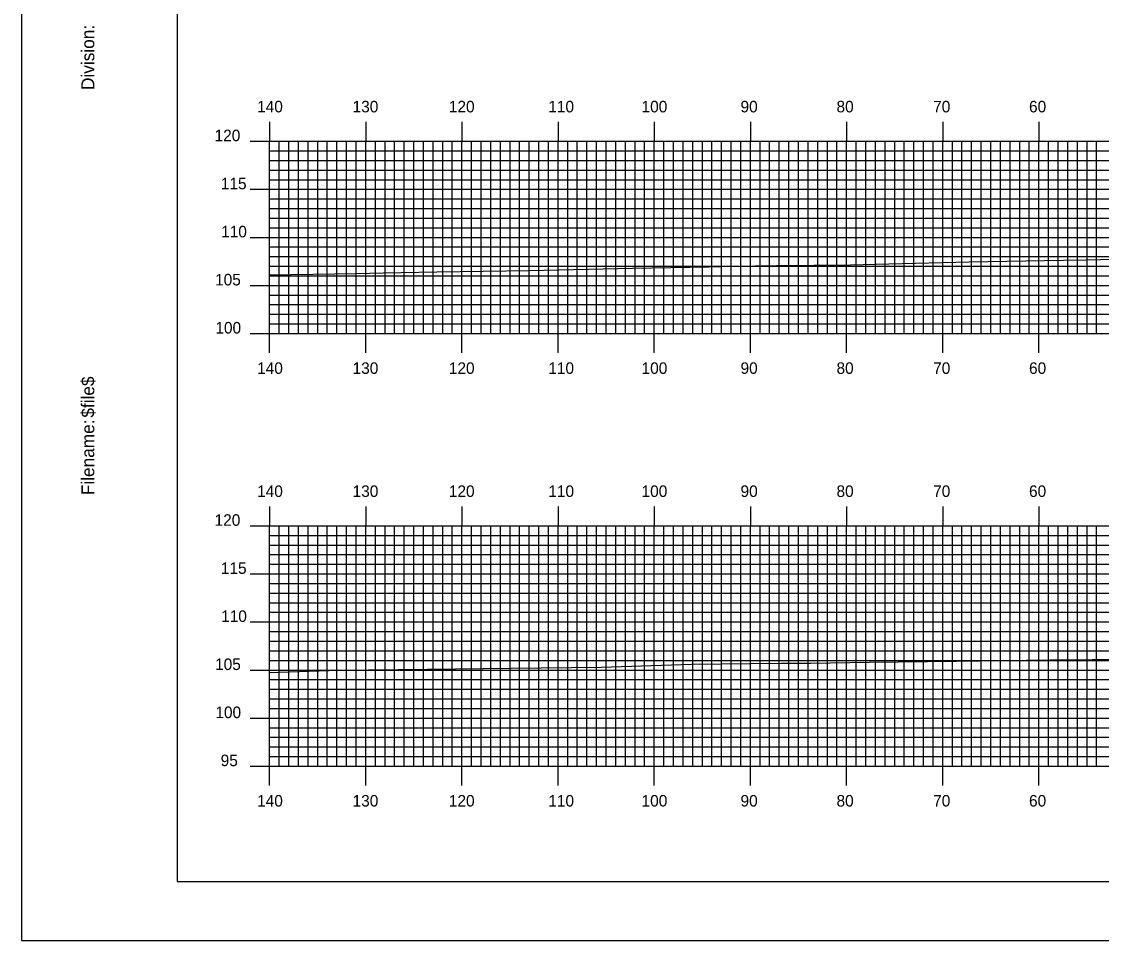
# Model space of a CAD drawing. Extents: x 1766120 to 1766463, y 442591 to 442811.
# Drawn here: x 1766119.6 to 1766231.9, y 442590.5 to 442686.1 of the extents above; entities that cross this region are included whole.
import ezdxf

# ---------------------------------------------------------------- set-up
doc = ezdxf.new("R2010")
doc.units = 0
for name, color, linetype in [('BORDER', 7, 'Continuous'), ('H_V ANNOTATION', 7, 'Continuous'), ('MAJOR', 7, 'Continuous'), ('MINOR', 7, 'Continuous'), ('PLOT BOUNDARY', 7, 'Continuous'), ('S_Roadway_Centerline', 7, 'Continuous')]:
    doc.layers.add(name, color=color, linetype=linetype)

msp = doc.modelspace()

# ---------------------------------------------------------------- linework, layer by layer
at = {"layer": 'BORDER'}
msp.add_lwpolyline([(1766135.8, 442596.67), (1766455.8, 442596.67), (1766455.8, 442806.67), (1766135.8, 442806.67)], close=True, dxfattribs=at)
at = {"layer": 'MAJOR'}
for p, q in [((1766145.4, 442675.67), (1766145.4, 442673.67)), ((1766155.4, 442675.67), (1766155.4, 442673.67)), ((1766165.4, 442675.67), (1766165.4, 442673.67)), ((1766175.4, 442675.67), (1766175.4, 442673.67)), ((1766185.4, 442675.67), (1766185.4, 442673.67)), ((1766195.4, 442675.67), (1766195.4, 442673.67)), ((1766205.4, 442675.67), (1766205.4, 442673.67)), ((1766215.4, 442675.67), (1766215.4, 442673.67)), ((1766225.4, 442675.67), (1766225.4, 442673.67)), ((1766143.39, 442673.67), (1766145.4, 442673.67)), ((1766145.4, 442673.67), (1766425.4, 442673.67)), ((1766145.4, 442653.67), (1766145.4, 442673.67)), ((1766145.4, 442653.67), (1766145.4, 442673.67)), ((1766145.4, 442673.67), (1766425.4, 442673.67)), ((1766155.4, 442653.67), (1766155.4, 442673.67)), ((1766165.4, 442653.67), (1766165.4, 442673.67)), ((1766175.4, 442653.67), (1766175.4, 442673.67)), ((1766185.4, 442653.67), (1766185.4, 442673.67)), ((1766195.4, 442653.67), (1766195.4, 442673.67)), ((1766205.4, 442653.67), (1766205.4, 442673.67)), ((1766215.4, 442653.67), (1766215.4, 442673.67)), ((1766225.4, 442653.67), (1766225.4, 442673.67)), ((1766143.39, 442668.67), (1766145.4, 442668.67)), ((1766145.4, 442668.67), (1766425.4, 442668.67)), ((1766143.39, 442663.67), (1766145.4, 442663.67)), ((1766145.4, 442663.67), (1766425.4, 442663.67)), ((1766143.39, 442658.67), (1766145.4, 442658.67)), ((1766145.4, 442658.67), (1766425.4, 442658.67)), ((1766143.39, 442653.67), (1766145.4, 442653.67)), ((1766145.4, 442653.67), (1766425.4, 442653.67)), ((1766145.4, 442653.67), (1766425.4, 442653.67)), ((1766145.4, 442651.66), (1766145.4, 442653.67)), ((1766155.4, 442651.66), (1766155.4, 442653.67)), ((1766165.4, 442651.66), (1766165.4, 442653.67)), ((1766175.4, 442651.66), (1766175.4, 442653.67)), ((1766185.4, 442651.66), (1766185.4, 442653.67)), ((1766195.4, 442651.66), (1766195.4, 442653.67)), ((1766205.4, 442651.66), (1766205.4, 442653.67)), ((1766215.4, 442651.66), (1766215.4, 442653.67)), ((1766225.4, 442651.66), (1766225.4, 442653.67)), ((1766145.4, 442635.67), (1766145.4, 442633.67)), ((1766155.4, 442635.67), (1766155.4, 442633.67)), ((1766165.4, 442635.67), (1766165.4, 442633.67)), ((1766175.4, 442635.67), (1766175.4, 442633.67)), ((1766185.4, 442635.67), (1766185.4, 442633.67)), ((1766195.4, 442635.67), (1766195.4, 442633.67)), ((1766205.4, 442635.67), (1766205.4, 442633.67)), ((1766215.4, 442635.67), (1766215.4, 442633.67)), ((1766225.4, 442635.67), (1766225.4, 442633.67)), ((1766143.39, 442633.67), (1766145.4, 442633.67)), ((1766145.4, 442633.67), (1766425.4, 442633.67)), ((1766145.4, 442608.67), (1766145.4, 442633.67)), ((1766145.4, 442608.67), (1766145.4, 442633.67)), ((1766145.4, 442633.67), (1766425.4, 442633.67)), ((1766155.4, 442608.67), (1766155.4, 442633.67)), ((1766165.4, 442608.67), (1766165.4, 442633.67)), ((1766175.4, 442608.67), (1766175.4, 442633.67)), ((1766185.4, 442608.67), (1766185.4, 442633.67)), ((1766195.4, 442608.67), (1766195.4, 442633.67)), ((1766205.4, 442608.67), (1766205.4, 442633.67)), ((1766215.4, 442608.67), (1766215.4, 442633.67)), ((1766225.4, 442608.67), (1766225.4, 442633.67)), ((1766143.39, 442628.67), (1766145.4, 442628.67)), ((1766145.4, 442628.67), (1766425.4, 442628.67)), ((1766143.39, 442623.67), (1766145.4, 442623.67)), ((1766145.4, 442623.67), (1766425.4, 442623.67)), ((1766143.39, 442618.67), (1766145.4, 442618.67)), ((1766145.4, 442618.67), (1766425.4, 442618.67)), ((1766143.39, 442613.67), (1766145.4, 442613.67)), ((1766145.4, 442613.67), (1766425.4, 442613.67)), ((1766143.39, 442608.67), (1766145.4, 442608.67)), ((1766145.4, 442608.67), (1766425.4, 442608.67)), ((1766145.4, 442608.67), (1766425.4, 442608.67)), ((1766145.4, 442606.66), (1766145.4, 442608.67)), ((1766155.4, 442606.66), (1766155.4, 442608.67)), ((1766165.4, 442606.66), (1766165.4, 442608.67)), ((1766175.4, 442606.66), (1766175.4, 442608.67)), ((1766185.4, 442606.66), (1766185.4, 442608.67)), ((1766195.4, 442606.66), (1766195.4, 442608.67)), ((1766205.4, 442606.66), (1766205.4, 442608.67)), ((1766215.4, 442606.66), (1766215.4, 442608.67)), ((1766225.4, 442606.66), (1766225.4, 442608.67))]:
    msp.add_line(p, q, dxfattribs=at)
at = {"layer": 'MINOR'}
for p, q in [((1766146.4, 442653.67), (1766146.4, 442673.67)), ((1766147.4, 442653.67), (1766147.4, 442673.67)), ((1766148.4, 442653.67), (1766148.4, 442673.67)), ((1766149.4, 442653.67), (1766149.4, 442673.67)), ((1766150.4, 442653.67), (1766150.4, 442673.67)), ((1766151.4, 442653.67), (1766151.4, 442673.67)), ((1766152.4, 442653.67), (1766152.4, 442673.67)), ((1766153.4, 442653.67), (1766153.4, 442673.67)), ((1766154.4, 442653.67), (1766154.4, 442673.67)), ((1766156.4, 442653.67), (1766156.4, 442673.67)), ((1766157.4, 442653.67), (1766157.4, 442673.67)), ((1766158.4, 442653.67), (1766158.4, 442673.67)), ((1766159.4, 442653.67), (1766159.4, 442673.67)), ((1766160.4, 442653.67), (1766160.4, 442673.67)), ((1766161.4, 442653.67), (1766161.4, 442673.67)), ((1766162.4, 442653.67), (1766162.4, 442673.67)), ((1766163.4, 442653.67), (1766163.4, 442673.67)), ((1766164.4, 442653.67), (1766164.4, 442673.67)), ((1766166.4, 442653.67), (1766166.4, 442673.67)), ((1766167.4, 442653.67), (1766167.4, 442673.67)), ((1766168.4, 442653.67), (1766168.4, 442673.67)), ((1766169.4, 442653.67), (1766169.4, 442673.67)), ((1766170.4, 442653.67), (1766170.4, 442673.67)), ((1766171.4, 442653.67), (1766171.4, 442673.67)), ((1766172.4, 442653.67), (1766172.4, 442673.67)), ((1766173.4, 442653.67), (1766173.4, 442673.67)), ((1766174.4, 442653.67), (1766174.4, 442673.67)), ((1766176.4, 442653.67), (1766176.4, 442673.67)), ((1766177.4, 442653.67), (1766177.4, 442673.67)), ((1766178.4, 442653.67), (1766178.4, 442673.67)), ((1766179.4, 442653.67), (1766179.4, 442673.67)), ((1766180.4, 442653.67), (1766180.4, 442673.67)), ((1766181.4, 442653.67), (1766181.4, 442673.67)), ((1766182.4, 442653.67), (1766182.4, 442673.67)), ((1766183.4, 442653.67), (1766183.4, 442673.67)), ((1766184.4, 442653.67), (1766184.4, 442673.67)), ((1766186.4, 442653.67), (1766186.4, 442673.67)), ((1766187.4, 442653.67), (1766187.4, 442673.67)), ((1766188.4, 442653.67), (1766188.4, 442673.67)), ((1766189.4, 442653.67), (1766189.4, 442673.67)), ((1766190.4, 442653.67), (1766190.4, 442673.67)), ((1766191.4, 442653.67), (1766191.4, 442673.67)), ((1766192.4, 442653.67), (1766192.4, 442673.67)), ((1766193.4, 442653.67), (1766193.4, 442673.67)), ((1766194.4, 442653.67), (1766194.4, 442673.67)), ((1766196.4, 442653.67), (1766196.4, 442673.67)), ((1766197.4, 442653.67), (1766197.4, 442673.67)), ((1766198.4, 442653.67), (1766198.4, 442673.67)), ((1766199.4, 442653.67), (1766199.4, 442673.67)), ((1766200.4, 442653.67), (1766200.4, 442673.67)), ((1766201.4, 442653.67), (1766201.4, 442673.67)), ((1766202.4, 442653.67), (1766202.4, 442673.67)), ((1766203.4, 442653.67), (1766203.4, 442673.67)), ((1766204.4, 442653.67), (1766204.4, 442673.67)), ((1766206.4, 442653.67), (1766206.4, 442673.67)), ((1766207.4, 442653.67), (1766207.4, 442673.67)), ((1766208.4, 442653.67), (1766208.4, 442673.67)), ((1766209.4, 442653.67), (1766209.4, 442673.67)), ((1766210.4, 442653.67), (1766210.4, 442673.67)), ((1766211.4, 442653.67), (1766211.4, 442673.67)), ((1766212.4, 442653.67), (1766212.4, 442673.67)), ((1766213.4, 442653.67), (1766213.4, 442673.67)), ((1766214.4, 442653.67), (1766214.4, 442673.67)), ((1766216.4, 442653.67), (1766216.4, 442673.67)), ((1766217.4, 442653.67), (1766217.4, 442673.67)), ((1766218.4, 442653.67), (1766218.4, 442673.67)), ((1766219.4, 442653.67), (1766219.4, 442673.67)), ((1766220.4, 442653.67), (1766220.4, 442673.67)), ((1766221.4, 442653.67), (1766221.4, 442673.67)), ((1766222.4, 442653.67), (1766222.4, 442673.67)), ((1766223.4, 442653.67), (1766223.4, 442673.67)), ((1766224.4, 442653.67), (1766224.4, 442673.67)), ((1766226.4, 442653.67), (1766226.4, 442673.67)), ((1766227.4, 442653.67), (1766227.4, 442673.67)), ((1766228.4, 442653.67), (1766228.4, 442673.67)), ((1766229.4, 442653.67), (1766229.4, 442673.67)), ((1766230.4, 442653.67), (1766230.4, 442673.67)), ((1766231.4, 442653.67), (1766231.4, 442673.67)), ((1766145.4, 442672.67), (1766425.4, 442672.67)), ((1766145.4, 442672.67), (1766147.4, 442672.67)), ((1766145.4, 442671.67), (1766425.4, 442671.67)), ((1766145.4, 442671.67), (1766147.4, 442671.67)), ((1766145.4, 442670.67), (1766425.4, 442670.67)), ((1766145.4, 442670.67), (1766147.4, 442670.67)), ((1766145.4, 442669.67), (1766425.4, 442669.67)), ((1766145.4, 442669.67), (1766147.4, 442669.67)), ((1766145.4, 442667.67), (1766425.4, 442667.67)), ((1766145.4, 442667.67), (1766147.4, 442667.67)), ((1766145.4, 442666.67), (1766425.4, 442666.67)), ((1766145.4, 442666.67), (1766147.4, 442666.67)), ((1766145.4, 442665.67), (1766425.4, 442665.67)), ((1766145.4, 442665.67), (1766147.4, 442665.67)), ((1766145.4, 442664.67), (1766425.4, 442664.67)), ((1766145.4, 442664.67), (1766147.4, 442664.67)), ((1766145.4, 442662.67), (1766425.4, 442662.67)), ((1766145.4, 442662.67), (1766147.4, 442662.67)), ((1766145.4, 442661.67), (1766425.4, 442661.67)), ((1766145.4, 442661.67), (1766147.4, 442661.67)), ((1766145.4, 442660.67), (1766425.4, 442660.67)), ((1766145.4, 442660.67), (1766147.4, 442660.67)), ((1766145.4, 442659.67), (1766425.4, 442659.67)), ((1766145.4, 442659.67), (1766147.4, 442659.67)), ((1766145.4, 442657.67), (1766425.4, 442657.67)), ((1766145.4, 442657.67), (1766147.4, 442657.67)), ((1766145.4, 442656.67), (1766425.4, 442656.67)), ((1766145.4, 442656.67), (1766147.4, 442656.67)), ((1766145.4, 442655.67), (1766425.4, 442655.67)), ((1766145.4, 442655.67), (1766147.4, 442655.67)), ((1766145.4, 442654.67), (1766425.4, 442654.67)), ((1766145.4, 442654.67), (1766147.4, 442654.67)), ((1766146.4, 442608.67), (1766146.4, 442633.67)), ((1766147.4, 442608.67), (1766147.4, 442633.67)), ((1766148.4, 442608.67), (1766148.4, 442633.67)), ((1766149.4, 442608.67), (1766149.4, 442633.67)), ((1766150.4, 442608.67), (1766150.4, 442633.67)), ((1766151.4, 442608.67), (1766151.4, 442633.67)), ((1766152.4, 442608.67), (1766152.4, 442633.67)), ((1766153.4, 442608.67), (1766153.4, 442633.67)), ((1766154.4, 442608.67), (1766154.4, 442633.67)), ((1766156.4, 442608.67), (1766156.4, 442633.67)), ((1766157.4, 442608.67), (1766157.4, 442633.67)), ((1766158.4, 442608.67), (1766158.4, 442633.67)), ((1766159.4, 442608.67), (1766159.4, 442633.67)), ((1766160.4, 442608.67), (1766160.4, 442633.67)), ((1766161.4, 442608.67), (1766161.4, 442633.67)), ((1766162.4, 442608.67), (1766162.4, 442633.67)), ((1766163.4, 442608.67), (1766163.4, 442633.67)), ((1766164.4, 442608.67), (1766164.4, 442633.67)), ((1766166.4, 442608.67), (1766166.4, 442633.67)), ((1766167.4, 442608.67), (1766167.4, 442633.67)), ((1766168.4, 442608.67), (1766168.4, 442633.67)), ((1766169.4, 442608.67), (1766169.4, 442633.67)), ((1766170.4, 442608.67), (1766170.4, 442633.67)), ((1766171.4, 442608.67), (1766171.4, 442633.67)), ((1766172.4, 442608.67), (1766172.4, 442633.67)), ((1766173.4, 442608.67), (1766173.4, 442633.67)), ((1766174.4, 442608.67), (1766174.4, 442633.67)), ((1766176.4, 442608.67), (1766176.4, 442633.67)), ((1766177.4, 442608.67), (1766177.4, 442633.67)), ((1766178.4, 442608.67), (1766178.4, 442633.67)), ((1766179.4, 442608.67), (1766179.4, 442633.67)), ((1766180.4, 442608.67), (1766180.4, 442633.67)), ((1766181.4, 442608.67), (1766181.4, 442633.67)), ((1766182.4, 442608.67), (1766182.4, 442633.67)), ((1766183.4, 442608.67), (1766183.4, 442633.67)), ((1766184.4, 442608.67), (1766184.4, 442633.67)), ((1766186.4, 442608.67), (1766186.4, 442633.67)), ((1766187.4, 442608.67), (1766187.4, 442633.67)), ((1766188.4, 442608.67), (1766188.4, 442633.67)), ((1766189.4, 442608.67), (1766189.4, 442633.67)), ((1766190.4, 442608.67), (1766190.4, 442633.67)), ((1766191.4, 442608.67), (1766191.4, 442633.67)), ((1766192.4, 442608.67), (1766192.4, 442633.67)), ((1766193.4, 442608.67), (1766193.4, 442633.67)), ((1766194.4, 442608.67), (1766194.4, 442633.67)), ((1766196.4, 442608.67), (1766196.4, 442633.67)), ((1766197.4, 442608.67), (1766197.4, 442633.67)), ((1766198.4, 442608.67), (1766198.4, 442633.67)), ((1766199.4, 442608.67), (1766199.4, 442633.67)), ((1766200.4, 442608.67), (1766200.4, 442633.67)), ((1766201.4, 442608.67), (1766201.4, 442633.67)), ((1766202.4, 442608.67), (1766202.4, 442633.67)), ((1766203.4, 442608.67), (1766203.4, 442633.67)), ((1766204.4, 442608.67), (1766204.4, 442633.67)), ((1766206.4, 442608.67), (1766206.4, 442633.67)), ((1766207.4, 442608.67), (1766207.4, 442633.67)), ((1766208.4, 442608.67), (1766208.4, 442633.67)), ((1766209.4, 442608.67), (1766209.4, 442633.67)), ((1766210.4, 442608.67), (1766210.4, 442633.67)), ((1766211.4, 442608.67), (1766211.4, 442633.67)), ((1766212.4, 442608.67), (1766212.4, 442633.67)), ((1766213.4, 442608.67), (1766213.4, 442633.67)), ((1766214.4, 442608.67), (1766214.4, 442633.67)), ((1766216.4, 442608.67), (1766216.4, 442633.67)), ((1766217.4, 442608.67), (1766217.4, 442633.67)), ((1766218.4, 442608.67), (1766218.4, 442633.67)), ((1766219.4, 442608.67), (1766219.4, 442633.67)), ((1766220.4, 442608.67), (1766220.4, 442633.67)), ((1766221.4, 442608.67), (1766221.4, 442633.67)), ((1766222.4, 442608.67), (1766222.4, 442633.67)), ((1766223.4, 442608.67), (1766223.4, 442633.67)), ((1766224.4, 442608.67), (1766224.4, 442633.67)), ((1766226.4, 442608.67), (1766226.4, 442633.67)), ((1766227.4, 442608.67), (1766227.4, 442633.67)), ((1766228.4, 442608.67), (1766228.4, 442633.67)), ((1766229.4, 442608.67), (1766229.4, 442633.67)), ((1766230.4, 442608.67), (1766230.4, 442633.67)), ((1766231.4, 442608.67), (1766231.4, 442633.67)), ((1766145.4, 442632.67), (1766425.4, 442632.67)), ((1766145.4, 442632.67), (1766147.4, 442632.67)), ((1766145.4, 442631.67), (1766425.4, 442631.67)), ((1766145.4, 442631.67), (1766147.4, 442631.67)), ((1766145.4, 442630.67), (1766425.4, 442630.67)), ((1766145.4, 442630.67), (1766147.4, 442630.67)), ((1766145.4, 442629.67), (1766425.4, 442629.67)), ((1766145.4, 442629.67), (1766147.4, 442629.67)), ((1766145.4, 442627.67), (1766425.4, 442627.67)), ((1766145.4, 442627.67), (1766147.4, 442627.67)), ((1766145.4, 442626.67), (1766425.4, 442626.67)), ((1766145.4, 442626.67), (1766147.4, 442626.67)), ((1766145.4, 442625.67), (1766425.4, 442625.67)), ((1766145.4, 442625.67), (1766147.4, 442625.67)), ((1766145.4, 442624.67), (1766425.4, 442624.67)), ((1766145.4, 442624.67), (1766147.4, 442624.67)), ((1766145.4, 442622.67), (1766425.4, 442622.67)), ((1766145.4, 442622.67), (1766147.4, 442622.67)), ((1766145.4, 442621.67), (1766425.4, 442621.67)), ((1766145.4, 442621.67), (1766147.4, 442621.67)), ((1766145.4, 442620.67), (1766425.4, 442620.67)), ((1766145.4, 442620.67), (1766147.4, 442620.67)), ((1766145.4, 442619.67), (1766425.4, 442619.67)), ((1766145.4, 442619.67), (1766147.4, 442619.67)), ((1766145.4, 442617.67), (1766425.4, 442617.67)), ((1766145.4, 442617.67), (1766147.4, 442617.67)), ((1766145.4, 442616.67), (1766425.4, 442616.67)), ((1766145.4, 442616.67), (1766147.4, 442616.67)), ((1766145.4, 442615.67), (1766425.4, 442615.67)), ((1766145.4, 442615.67), (1766147.4, 442615.67)), ((1766145.4, 442614.67), (1766425.4, 442614.67)), ((1766145.4, 442614.67), (1766147.4, 442614.67)), ((1766145.4, 442612.67), (1766425.4, 442612.67)), ((1766145.4, 442612.67), (1766147.4, 442612.67)), ((1766145.4, 442611.67), (1766425.4, 442611.67)), ((1766145.4, 442611.67), (1766147.4, 442611.67)), ((1766145.4, 442610.67), (1766425.4, 442610.67)), ((1766145.4, 442610.67), (1766147.4, 442610.67)), ((1766145.4, 442609.67), (1766425.4, 442609.67)), ((1766145.4, 442609.67), (1766147.4, 442609.67))]:
    msp.add_line(p, q, dxfattribs=at)
at = {"layer": 'PLOT BOUNDARY'}
msp.add_lwpolyline([(1766119.61, 442590.55), (1766459.61, 442590.55), (1766459.61, 442810.55), (1766119.61, 442810.55)], close=True, dxfattribs=at)
at = {"layer": 'S_Roadway_Centerline'}
for points in [[(1766145.4, 442659.78), (1766154.42, 442659.91), (1766157.22, 442659.97), (1766162.79, 442660.08), (1766172.42, 442660.24), (1766183.13, 442660.48), (1766191.12, 442660.61), (1766193.57, 442660.67), (1766198.16, 442660.74), (1766205.79, 442660.82), (1766209.78, 442660.93), (1766218.13, 442661.12), (1766227.97, 442661.29), (1766230.29, 442661.32), (1766234.85, 442661.44)], [(1766145.4, 442618.41), (1766152.62, 442618.65), (1766161.82, 442618.76), (1766170.51, 442618.85), (1766179.91, 442618.95), (1766189.26, 442619.27), (1766198.59, 442619.39), (1766201.69, 442619.39), (1766207.74, 442619.48), (1766216.83, 442619.58), (1766226.53, 442619.72), (1766235.34, 442619.81)]]:
    msp.add_lwpolyline(points, dxfattribs=at)

# ---------------------------------------------------------------- texts
at = {"layer": 'BORDER'}
for s, p in [('Division:', (1766127.17, 442679)), ('$file$', (1766127.17, 442644.92)), ('Filename:', (1766127.17, 442636.86))]:
    msp.add_text(s, height=1.339, rotation=90, dxfattribs=at).set_placement(p)
at = {"layer": 'H_V ANNOTATION'}
for s, p in [('140', (1766144.1, 442676.67)), ('130', (1766154.03, 442676.67)), ('120', (1766164.04, 442676.67)), ('110', (1766174.38, 442676.67)), ('100', (1766184.08, 442676.67)), ('90', (1766194.37, 442676.67)), ('80', (1766204.35, 442676.67)), ('70', (1766214.4, 442676.67)), ('60', (1766224.37, 442676.67)), ('120', (1766139.68, 442673.67)), ('115', (1766140.33, 442668.67)), ('110', (1766140.36, 442663.67)), ('105', (1766139.73, 442658.67)), ('100', (1766139.76, 442653.67)), ('140', (1766144.1, 442649.47)), ('130', (1766154.03, 442649.47)), ('120', (1766164.04, 442649.47)), ('110', (1766174.38, 442649.47)), ('100', (1766184.08, 442649.47)), ('90', (1766194.37, 442649.47)), ('80', (1766204.35, 442649.47)), ('70', (1766214.4, 442649.47)), ('60', (1766224.37, 442649.47)), ('140', (1766144.1, 442636.67)), ('130', (1766154.03, 442636.67)), ('120', (1766164.04, 442636.67)), ('110', (1766174.38, 442636.67)), ('100', (1766184.08, 442636.67)), ('90', (1766194.37, 442636.67)), ('80', (1766204.35, 442636.67)), ('70', (1766214.4, 442636.67)), ('60', (1766224.37, 442636.67)), ('120', (1766139.68, 442633.67)), ('115', (1766140.33, 442628.67)), ('110', (1766140.36, 442623.67)), ('105', (1766139.73, 442618.67)), ('100', (1766139.76, 442613.67)), ('95', (1766140.31, 442608.67)), ('140', (1766144.1, 442604.47)), ('130', (1766154.03, 442604.47)), ('120', (1766164.04, 442604.47)), ('110', (1766174.38, 442604.47)), ('100', (1766184.08, 442604.47)), ('90', (1766194.37, 442604.47)), ('80', (1766204.35, 442604.47)), ('70', (1766214.4, 442604.47)), ('60', (1766224.37, 442604.47))]:
    msp.add_text(s, height=1.2, dxfattribs=at).set_placement(p)
at = {"layer": 'MAJOR'}
for p in [(1766145.39, 442653.67), (1766145.39, 442608.67)]:
    msp.add_text('-', height=0.012, dxfattribs=at).set_placement(p)

doc.saveas('drawing.dxf')
